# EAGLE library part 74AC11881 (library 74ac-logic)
COMPARATOR
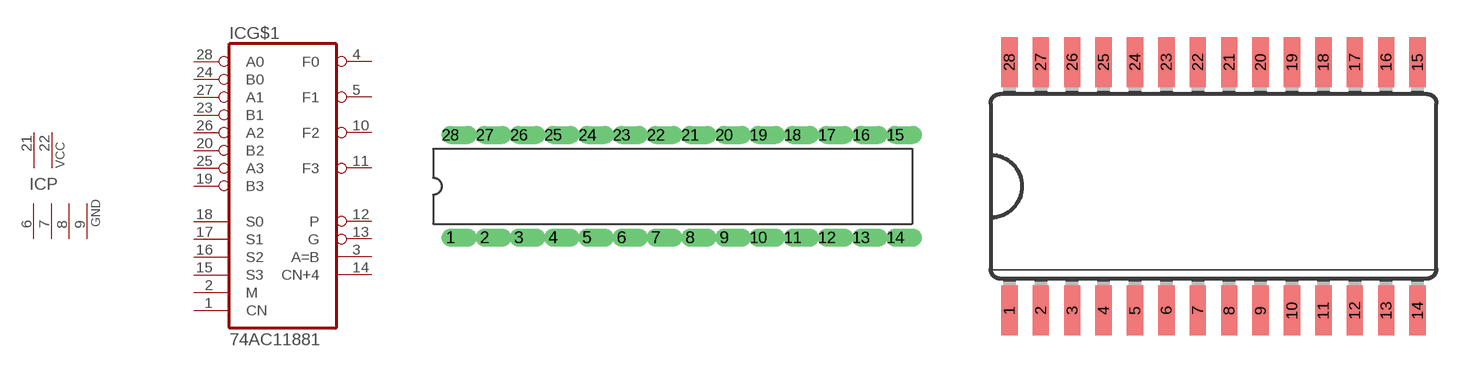
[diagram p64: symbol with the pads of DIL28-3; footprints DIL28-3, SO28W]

Designator prefix IC; gates G$1=7411881 P=2PWR4GND

## 74AC11881  [DIL28-3]
1  G$1:CN  in
2  G$1:M  in
3  G$1:A=B  out
4  G$1:F0  out
5  G$1:F1  out
6  P:GND  pwr
7  P:GND  pwr
8  P:GND  pwr
9  P:GND  pwr
10  G$1:F2  out
11  G$1:F3  out
12  G$1:P  out
13  G$1:G  out
14  G$1:CN+4  out
15  G$1:S3  in
16  G$1:S2  in
17  G$1:S1  in
18  G$1:S0  in
19  G$1:B3  in
20  G$1:B2  in
21  P:VCC  pwr
22  P:VCC  pwr
23  G$1:B1  in
24  G$1:B0  in
25  G$1:A3  in
26  G$1:A2  in
27  G$1:A1  in
28  G$1:A0  in

## 74AC11881D  [SO28W]
Pads as for DIL28-3

## Footprint DIL28-3 (pad centres in mm)
Dual In Line 0.3 inch
drill 0.813 offset: 1 -16.51,-3.81; 2 -13.97,-3.81; 3 -11.43,-3.81; 4 -8.89,-3.81; 5 -6.35,-3.81; 6 -3.81,-3.81; 7 -1.27,-3.81; 8 1.27,-3.81; 9 3.81,-3.81; 10 6.35,-3.81; 11 8.89,-3.81; 12 11.43,-3.81; 13 13.97,-3.81; 14 16.51,-3.81; 15 16.51,3.81; 16 13.97,3.81; 17 11.43,3.81; 18 8.89,3.81; 19 6.35,3.81; 20 3.81,3.81; 21 1.27,3.81; 22 -1.27,3.81; 23 -3.81,3.81; 24 -6.35,3.81; 25 -8.89,3.81; 26 -11.43,3.81; 27 -13.97,3.81; 28 -16.51,3.81

## Footprint SO28W (pad centres in mm)
Wide Small Outline package 300 mil
smd 0.66 x 2.032: 1 -8.255,-5.029; 2 -6.985,-5.029; 3 -5.715,-5.029; 4 -4.445,-5.029; 5 -3.175,-5.029; 6 -1.905,-5.029; 7 -0.635,-5.029; 8 0.635,-5.029; 9 1.905,-5.029; 10 3.175,-5.029; 11 4.445,-5.029; 12 5.715,-5.029; 13 6.985,-5.029; 14 8.255,-5.029; 15 8.255,5.029; 16 6.985,5.029; 17 5.715,5.029; 18 4.445,5.029; 19 3.175,5.029; 20 1.905,5.029; 21 0.635,5.029; 22 -0.635,5.029; 23 -1.905,5.029; 24 -3.175,5.029; 25 -4.445,5.029; 26 -5.715,5.029; 27 -6.985,5.029; 28 -8.255,5.029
